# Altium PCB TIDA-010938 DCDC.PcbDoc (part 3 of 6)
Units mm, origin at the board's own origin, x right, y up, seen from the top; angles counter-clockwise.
Board outline 280 x 174.95 mm, 4 copper layers (Top Layer, Layer 1, Layer 2, Bottom Layer), stack 1.787 mm thick; 409 components, 218 nets, 1371 pads, 2268 vias.
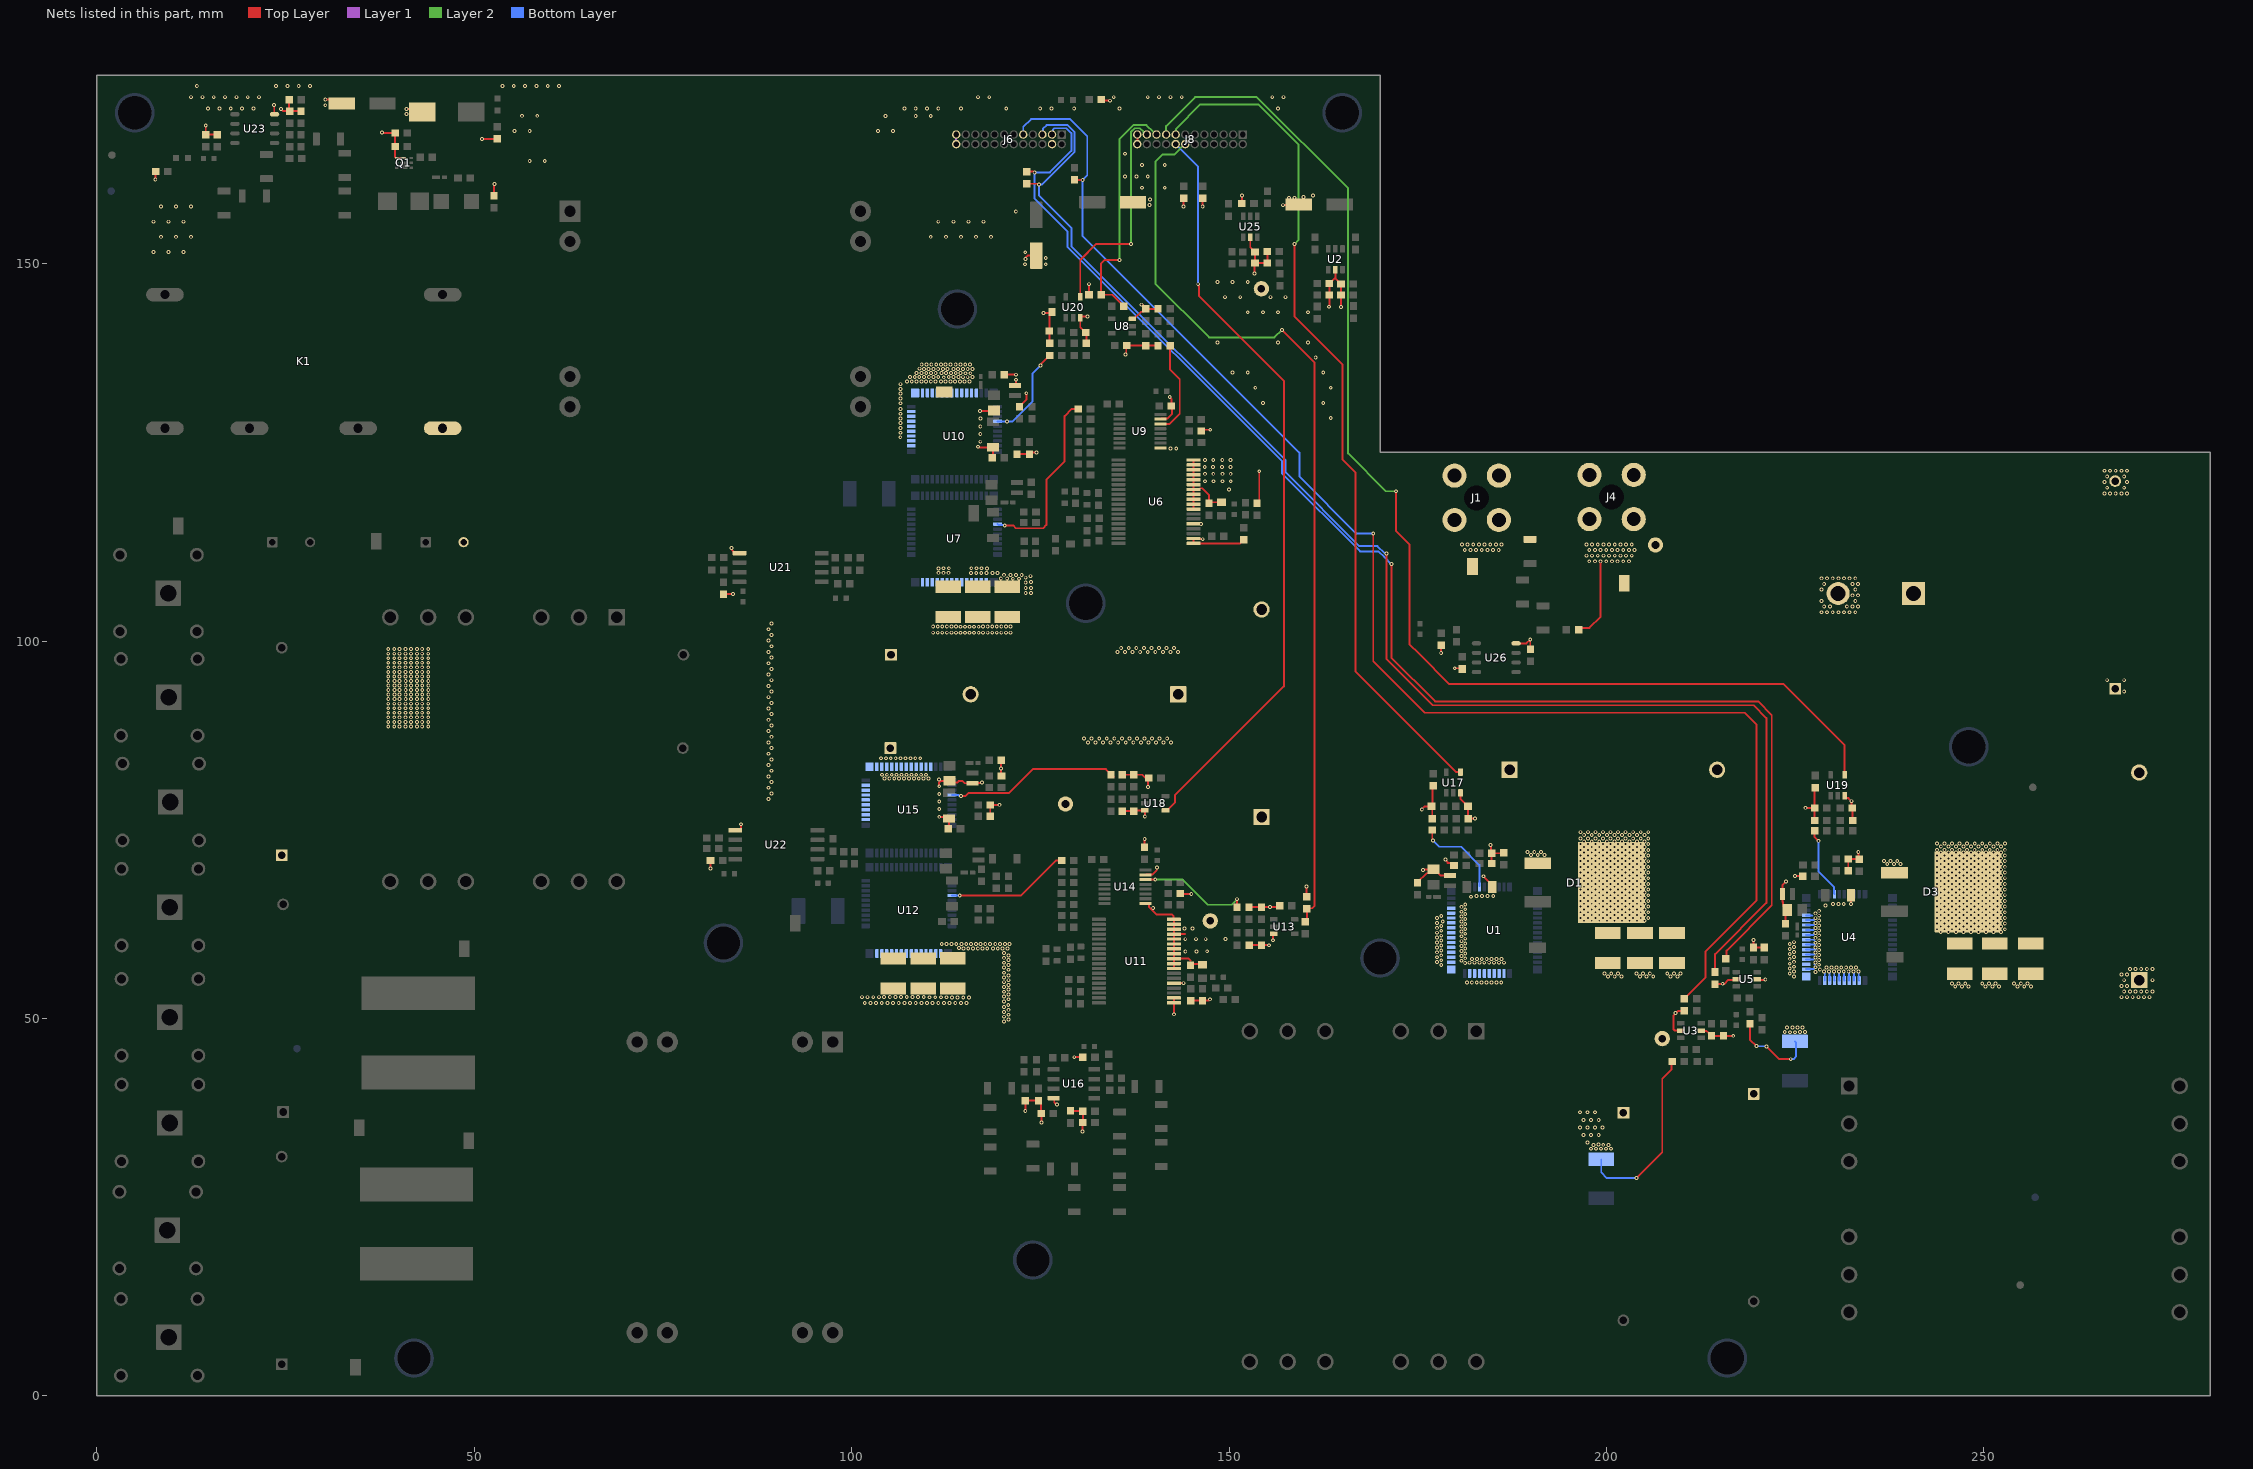
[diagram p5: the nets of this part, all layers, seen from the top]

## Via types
v1: diameter 0.508, hole 0.254, Top Layer to Bottom Layer, tented both sides, 1783 vias
v2: diameter 0.508, hole 0.254, Top Layer to Bottom Layer, 485 vias

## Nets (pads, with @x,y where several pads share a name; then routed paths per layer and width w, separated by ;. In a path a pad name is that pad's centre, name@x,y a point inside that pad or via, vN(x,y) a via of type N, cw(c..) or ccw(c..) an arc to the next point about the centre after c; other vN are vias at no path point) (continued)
CS_Boost1-: C19.1 J6.9 R146.2 | length 193.6
  Top Layer w0.254: C19.1@129.5,161.1 v1(130.6,161.1) ; v1(169.096,114.25) 169.096,97.304 175.9,90.5 218.3,90.5 219.9,88.9 219.9,65.659 213.1,58.859 213.1,55.425 210.3,52.625 R146.2@210.3,52.6
  Bottom Layer w0.254: J6.9@122.73,167.116 122.73,168.141 123.755,169.165 128.957,169.165 131.205,166.917 131.205,161.705 v1(130.6,161.1) 130.6,153.671 159.302,124.969 159.302,121.811 166.863,114.25 v1(169.096,114.25)
CS_Boost2+: C112.2 J6.3 R19.2 | length 186.7
  Top Layer w0.254: C112.2@123.184,162.2 124.077,162.2 124.174,162.103 v1(124.242,162.103) ; v1(171.5,110.207) 171.5,97.8 177.3,92 220.1,92 221.9,90.2 221.9,64.967 215.932,59 215.932,58.032 R19.2@215.8,57.9
  Bottom Layer w0.254: J6.3@126.54,167.116 126.675,167.251 126.675,167.804 126.823,167.953 128.455,167.953 129.1,167.308 129.1,164.936 126.267,162.103 v1(124.242,162.103) 124.242,158.625 128.585,154.283 128.585,152.276 156.995,123.865 156.995,122.259 167.37,111.884 169.795,111.884 170.592,111.087 170.62,111.087 v1(171.5,110.207)
CS_Boost2-: C112.1 J6.5 R72.2 | length 189.9
  Top Layer w0.254: C112.1@123.184,160.6 124.631,160.6 124.731,160.5 v1(124.8,160.5) ; v1(170.854,111.604) 170.854,97.646 177,91.5 219.5,91.5 221.2,89.8 221.2,65.323 214.4,58.523 R72.2@214.4,56.154
  Bottom Layer w0.254: J6.5@125.27,167.116 125.335,167.181 125.335,167.874 125.818,168.357 128.623,168.357 129.504,167.476 129.504,164.768 125.236,160.5 v1(124.8,160.5) 124.8,159.061 129.106,154.755 129.106,152.326 157.478,123.954 157.478,122.348 167.229,112.596 169.654,112.596 170.598,111.652 170.805,111.652 v1(170.854,111.604)
DC_Bus+: C3.1 C4.1 C10.1 C24.1 C100.1 C101.1 C106.1 C110.1 C111.1 C113.1 C114.2 C127.1 C130.1 C131.1 C135.1 C140.1 C141.1 C143.2 D1.1 D1.3 D3.1 D3.3 J1.1 R21.1 TP40.1 U7.2 U7.3 U7.4 U7.5 U7.6 U7.7 U7.8 U7.9 U7.10 U7.11 U7.12 U7.13 U7.14 U7.15 U12.2 U12.3 U12.4 U12.5 U12.6 U12.7 U12.8 U12.9 U12.10 U12.11 U12.12 U12.13 U12.14 U12.15
  other v1: 120.17,49.582 120.758,49.869 120.17,50.232 120.758,50.493 120.17,50.856 120.758,51.143 120.17,51.506 120.744,51.803 120.17,52.259 120.758,52.547 120.17,52.909 120.758,53.17 120.17,53.533 120.758,53.82 120.17,54.183 120.758,54.444 120.17,54.807 120.758,55.072 120.17,55.435 120.758,55.696 120.17,56.058 120.758,56.456 120.17,56.761 120.758,57.08 120.17,57.385 120.758,57.73 120.17,58.035 120.758,58.353 120.17,58.658 114.811,59.284 115.435,59.284 116.085,59.284 116.708,59.284 117.336,59.284 117.96,59.284 118.72,59.284 119.344,59.284 119.994,59.284 120.618,59.284 114.218,59.322 111.928,59.879 112.578,59.879 113.202,59.879 113.852,59.879 114.524,59.873 115.174,59.873 115.798,59.873 116.448,59.873 117.071,59.873 117.699,59.873 118.323,59.873 119.025,59.873 119.649,59.873 120.299,59.873 120.923,59.873 244.297,61.44 245.297,61.44 246.297,61.44 247.297,61.44 248.297,61.44 249.297,61.44 250.297,61.44 251.297,61.44 252.291,61.44 243.79,61.817 244.79,61.817 245.79,61.817 246.79,61.817 247.79,61.817 248.79,61.817 249.79,61.817 250.79,61.817 251.79,61.817 252.784,61.817 244.297,62.191 245.297,62.191 246.297,62.191 247.297,62.191 248.297,62.191 249.297,62.191 250.297,62.191 251.297,62.191 252.291,62.192 243.79,62.569 244.79,62.569 245.79,62.569 246.79,62.569 247.79,62.569 248.79,62.569 249.79,62.569 250.79,62.569 251.79,62.569 252.784,62.569 197.047,62.94 198.047,62.94 199.047,62.94 200.047,62.94 201.047,62.94 202.047,62.94 203.047,62.94 204.047,62.94 205.041,62.94 244.297,62.943 245.297,62.943 246.297,62.943 247.297,62.943 248.297,62.943 249.297,62.943 250.297,62.943 251.297,62.943 252.291,62.944 196.54,63.317 197.54,63.317 198.54,63.317 199.54,63.317 200.54,63.317 201.54,63.317 202.54,63.317 203.54,63.317 204.54,63.317 205.534,63.317 243.79,63.321 244.79,63.321 245.79,63.321 246.79,63.321 247.79,63.321 248.79,63.321 249.79,63.321 250.79,63.321 251.79,63.321 252.784,63.321 197.047,63.691 198.047,63.691 199.047,63.691 200.047,63.691 201.047,63.691 202.047,63.691 203.047,63.691 204.047,63.691 205.041,63.692 244.297,63.695 245.297,63.695 246.297,63.695 247.297,63.695 248.297,63.695 249.297,63.695 250.297,63.695 251.297,63.695 252.291,63.696 196.54,64.069 197.54,64.069 198.54,64.069 199.54,64.069 200.54,64.069 201.54,64.069 202.54,64.069 203.54,64.069 204.54,64.069 205.534,64.069 243.79,64.073 244.79,64.073 245.79,64.073 246.79,64.073 247.79,64.073 248.79,64.073 249.79,64.073 250.79,64.073 251.79,64.073 252.784,64.073 197.047,64.443 198.047,64.443 199.047,64.443 200.047,64.443 201.047,64.443 202.047,64.443 203.047,64.443 204.047,64.443 205.041,64.444 244.297,64.447 245.297,64.447 246.297,64.447 247.297,64.447 248.297,64.447 249.297,64.447 250.297,64.447 251.297,64.447 252.291,64.448 196.54,64.821 197.54,64.821 198.54,64.821 199.54,64.821 200.54,64.821 201.54,64.821 202.54,64.821 203.54,64.821 204.54,64.821 205.534,64.821 243.79,64.825 244.79,64.825 245.79,64.825 246.79,64.825 247.79,64.825 248.79,64.825 249.79,64.825 250.79,64.825 251.79,64.825 252.784,64.825 197.047,65.195 198.047,65.195 199.047,65.195 200.047,65.195 201.047,65.195 202.047,65.195 203.047,65.195 204.047,65.195 205.041,65.196 244.297,65.199 245.297,65.199 246.297,65.199 247.297,65.199 248.297,65.199 249.297,65.199 250.297,65.199 251.297,65.199 252.291,65.199 196.54,65.573 197.54,65.573 198.54,65.573 199.54,65.573 200.54,65.573 201.54,65.573 202.54,65.573 203.54,65.573 204.54,65.573 205.534,65.573 243.79,65.577 244.79,65.577 245.79,65.577 246.79,65.577 247.79,65.577 248.79,65.577 249.79,65.577 250.79,65.577 251.79,65.577 252.784,65.577 197.047,65.947 198.047,65.947 199.047,65.947 200.047,65.947 201.047,65.947 202.047,65.947 203.047,65.947 204.047,65.947 205.041,65.948 244.297,65.951 245.297,65.951 246.297,65.951 247.297,65.951 248.297,65.951 249.297,65.951 250.297,65.951 251.297,65.951 252.291,65.951 196.54,66.325 197.54,66.325 198.54,66.325 199.54,66.325 200.54,66.325 201.54,66.325 202.54,66.325 203.54,66.325 204.54,66.325 205.534,66.325 243.79,66.329 244.79,66.329 245.79,66.329 246.79,66.329 247.79,66.329 248.79,66.329 249.79,66.329 250.79,66.329 251.79,66.329 252.784,66.329 197.047,66.699 198.047,66.699 199.047,66.699 200.047,66.699 201.047,66.699 202.047,66.699 203.047,66.699 204.047,66.699 205.041,66.699 244.297,66.703 245.297,66.703 246.297,66.703 247.297,66.703 248.297,66.703 249.297,66.703 250.297,66.703 251.297,66.703 252.291,66.703 196.54,67.077 197.54,67.077 198.54,67.077 199.54,67.077 200.54,67.077 201.54,67.077 202.54,67.077 203.54,67.077 204.54,67.077 205.534,67.077 243.79,67.08 244.79,67.08 245.79,67.08 246.79,67.08 247.79,67.08 248.79,67.08 249.79,67.08 250.79,67.08 251.79,67.08 252.784,67.081 197.047,67.451 198.047,67.451 199.047,67.451 200.047,67.451 201.047,67.451 202.047,67.451 203.047,67.451 204.047,67.451 205.041,67.451 244.297,67.455 245.297,67.455 246.297,67.455 247.297,67.455 248.297,67.455 249.297,67.455 250.297,67.455 251.297,67.455 252.291,67.455 196.54,67.829 197.54,67.829 198.54,67.829 199.54,67.829 200.54,67.829 201.54,67.829 202.54,67.829 203.54,67.829 204.54,67.829 205.534,67.829 243.79,67.832 244.79,67.832 245.79,67.832 246.79,67.832 247.79,67.832 248.79,67.832 249.79,67.832 250.79,67.832 251.79,67.832 252.784,67.833 197.047,68.203 198.047,68.203 199.047,68.203 200.047,68.203 201.047,68.203 202.047,68.203 203.047,68.203 204.047,68.203 205.041,68.203 244.297,68.207 245.297,68.207 246.297,68.207 247.297,68.207 248.297,68.207 249.297,68.207 250.297,68.207 251.297,68.207 252.291,68.207 196.54,68.58 197.54,68.58 198.54,68.58 199.54,68.58 200.54,68.58 201.54,68.58 202.54,68.58 203.54,68.58 204.54,68.58 205.534,68.581 243.79,68.584 244.79,68.584 245.79,68.584 246.79,68.584 247.79,68.584 248.79,68.584 249.79,68.584 250.79,68.584 251.79,68.584 252.784,68.585 197.047,68.955 198.047,68.955 199.047,68.955 200.047,68.955 201.047,68.955 202.047,68.955 203.047,68.955 204.047,68.955 205.041,68.955 244.297,68.959 245.297,68.959 246.297,68.959 247.297,68.959 248.297,68.959 249.297,68.959 250.297,68.959 251.297,68.959 252.291,68.959 196.54,69.332 197.54,69.332 198.54,69.332 199.54,69.332 200.54,69.332 201.54,69.332 202.54,69.332 203.54,69.332 204.54,69.332 205.534,69.333 243.79,69.336 244.79,69.336 245.79,69.336 246.79,69.336 247.79,69.336 248.79,69.336 249.79,69.336 250.79,69.336 251.79,69.336 252.784,69.337 197.047,69.707 198.047,69.707 199.047,69.707 200.047,69.707 201.047,69.707 202.047,69.707 203.047,69.707 204.047,69.707 205.041,69.707 244.297,69.711 245.297,69.711 246.297,69.711 247.297,69.711 248.297,69.711 249.297,69.711 250.297,69.711 251.297,69.711 252.291,69.711 196.54,70.084 197.54,70.084 198.54,70.084 199.54,70.084 200.54,70.084 201.54,70.084 202.54,70.084 203.54,70.084 204.54,70.084 205.534,70.085 243.79,70.088 244.79,70.088 245.79,70.088 246.79,70.088 247.79,70.088 248.79,70.088 249.79,70.088 250.79,70.088 251.79,70.088 252.784,70.089 197.047,70.459 198.047,70.459 199.047,70.459 200.047,70.459 201.047,70.459 202.047,70.459 203.047,70.459 204.047,70.459 205.041,70.459 237.206,70.462 238.094,70.462 238.981,70.462 244.297,70.463 245.297,70.463 246.297,70.463 247.297,70.463 248.297,70.463 249.297,70.463 250.297,70.463 251.297,70.463 252.291,70.463 196.54,70.836 197.54,70.836 198.54,70.836 199.54,70.836 200.54,70.836 201.54,70.836 202.54,70.836 203.54,70.836 204.54,70.836 205.534,70.837 243.79,70.84 244.79,70.84 245.79,70.84 246.79,70.84 247.79,70.84 248.79,70.84 249.79,70.84 250.79,70.84 251.79,70.84 252.784,70.84 236.753,70.883 237.64,70.883 238.527,70.883 197.047,71.211 198.047,71.211 199.047,71.211 200.047,71.211 201.047,71.211 202.047,71.211 203.047,71.211 204.047,71.211 205.041,71.211 244.297,71.214 245.297,71.214 246.297,71.214 247.297,71.214 248.297,71.214 249.297,71.214 250.297,71.214 251.297,71.214 252.291,71.215 196.54,71.588 197.54,71.588 198.54,71.588 199.54,71.588 200.54,71.588 201.54,71.588 202.54,71.588 203.54,71.588 204.54,71.588 205.534,71.589 243.79,71.592 244.79,71.592 245.79,71.592 246.79,71.592 247.79,71.592 248.79,71.592 249.79,71.592 250.79,71.592 251.79,71.592 252.784,71.592 190.007,71.648 190.894,71.648 191.782,71.648 197.047,71.963 198.047,71.963 199.047,71.963 200.047,71.963 201.047,71.963 202.047,71.963 203.047,71.963 204.047,71.963 205.041,71.963 244.297,71.966 245.297,71.966 246.297,71.966 247.297,71.966 248.297,71.966 249.297,71.966 250.297,71.966 251.297,71.966 252.291,71.967 189.554,72.07 190.441,72.07 191.328,72.07 196.54,72.34 197.54,72.34 198.54,72.34 199.54,72.34 200.54,72.34 201.54,72.34 202.54,72.34 203.54,72.34 204.54,72.34 205.534,72.34 243.79,72.344 244.79,72.344 245.79,72.344 246.79,72.344 247.79,72.344 248.79,72.344 249.79,72.344 250.79,72.344 251.79,72.344 252.784,72.344 197.047,72.714 198.047,72.714 199.047,72.714 200.047,72.714 201.047,72.714 202.047,72.714 203.047,72.714 204.047,72.714 205.041,72.715 244.3,72.8 245.3,72.8 246.3,72.8 247.3,72.8 248.3,72.8 249.3,72.8 250.3,72.8 251.3,72.8 252.293,72.8 196.54,73.092 197.54,73.092 198.54,73.092 199.54,73.092 200.54,73.092 201.54,73.092 202.54,73.092 203.54,73.092 204.54,73.092 205.534,73.092 243.793,73.178 244.793,73.178 245.793,73.178 246.793,73.178 247.793,73.178 248.793,73.178 249.793,73.178 250.793,73.178 251.793,73.178 252.786,73.178 197.047,73.466 198.047,73.466 199.047,73.466 200.047,73.466 201.047,73.466 202.047,73.466 203.047,73.466 204.047,73.466 205.041,73.467 196.54,73.844 197.54,73.844 198.54,73.844 199.54,73.844 200.54,73.844 201.54,73.844 202.54,73.844 203.54,73.844 204.54,73.844 205.534,73.844 197.05,74.3 198.05,74.3 199.05,74.3 200.05,74.3 201.05,74.3 202.05,74.3 203.05,74.3 204.05,74.3 205.043,74.3 196.543,74.678 197.543,74.678 198.543,74.678 199.543,74.678 200.543,74.678 201.543,74.678 202.543,74.678 203.543,74.678 204.543,74.678 205.536,74.678 131.306,86.58 132.307,86.58 133.307,86.58 134.307,86.58 135.308,86.58 136.308,86.58 137.309,86.58 138.309,86.58 139.31,86.58 140.31,86.58 141.311,86.58 142.311,86.58 130.791,87.08 131.791,87.08 132.792,87.08 133.792,87.08 134.792,87.08 135.793,87.08 136.793,87.08 137.794,87.08 138.794,87.08 139.795,87.08 140.795,87.08 141.796,87.08 135.22,98.572 136.22,98.572 137.221,98.572 138.221,98.572 139.222,98.572 140.222,98.572 141.222,98.572 142.223,98.572 143.223,98.572 135.705,99.072 136.705,99.072 137.706,99.072 138.706,99.072 139.707,99.072 140.707,99.072 141.708,99.072 142.708,99.072 123.051,106.38 123.756,106.38 123.051,107.032 123.76,107.049 123.051,107.746 123.756,107.822 121.344,108.262 122.18,108.255 119.754,108.3 120.6,108.3 123.051,108.398 123.7,108.6 121.019,108.755 121.781,108.755 120.191,108.779 122.519,108.761 118.655,109.005 119.311,109.005 111.478,109.048 112.149,109.048 112.833,109.048 115.817,109.042 116.501,109.042 117.158,109.042 117.85,109.038 117.906,109.611 111.499,109.637 115.845,109.645 116.529,109.645 117.186,109.645 112.17,109.651 112.861,109.651
  other v2: 268.223,52.817 268.973,52.817 269.723,52.817 270.473,52.817 271.223,52.817 271.973,52.817 268.598,53.567 269.348,53.567 270.098,53.567 270.848,53.567 271.598,53.567 272.348,53.567 268.223,54.317 268.973,54.317 268.598,55.067 272.348,55.067 268.223,55.817 268.973,55.817 269.348,56.567 270.098,56.567 270.848,56.567 271.598,56.567 272.348,56.567 228.473,103.817 229.223,103.817 229.973,103.817 230.723,103.817 231.473,103.817 232.223,103.817 232.973,103.817 228.848,104.567 229.598,104.567 231.848,104.567 232.598,104.567 233.348,104.567 228.473,105.317 232.973,105.317 232.598,106.067 233.348,106.067 228.473,106.817 232.973,106.817 228.848,107.567 232.598,107.567 233.348,107.567 228.473,108.317 229.223,108.317 229.973,108.317 230.723,108.317 231.473,108.317 232.223,108.317 232.973,108.317 181.223,112.067 181.973,112.067 182.723,112.067 183.473,112.067 184.223,112.067 184.973,112.067 185.723,112.067 180.848,112.817 181.598,112.817 182.348,112.817 183.098,112.817 183.848,112.817 184.598,112.817 185.348,112.817 186.098,112.817 265.973,119.567 266.723,119.567 267.473,119.567 268.223,119.567 268.973,119.567 266.348,120.317 268.598,120.317 265.973,121.067 268.973,121.067 266.348,121.817 268.598,121.817 265.973,122.567 266.723,122.567 267.473,122.567 268.223,122.567 268.973,122.567
DC_Bus-: C1.1 C2.1 C3.2 C4.2 C5.2 C6.2 C7.1 C8.1 C9.1 C10.2 C11.1 C12.1 C13.2 C14.1 C15.1 C16.2 C17.2 C20.2 C21.1 C22.1 C23.1 C24.2 C25.1 C26.1 C27.2 C28.1 C29.1 C31.1 C32.2 C39.1 C43.1 C47.1 C49.2 C50.1 C52.2 C57.2 C58.1 C59.2 C60.1 C61.1 C62.1 C64.1 C65.2 C67.2 C73.1 C77.1 C78.2 C81.1 C82.2 C83.2 C84.1 C86.2 C87.2 C91.2 C92.1 C93.2 C94.1 C95.1 C96.1 C97.2 C98.1 C99.2 C100.2 C101.2 C102.1 C103.1 C104.1 C105.1 C106.2 C107.1 C108.1 C110.2 C111.2 C113.2 C114.1 C115.2 C116.1 C117.2 C118.1 C119.1 C120.1 C121.2 C122.1 C123.1 C124.2 C125.2 C127.2 C128.2 C129.2 C130.2 C131.2 C132.1 C135.2 C140.2 C141.2 C142.1 C143.1 C144.2 C146.2 C152.1 C155.1 J4.1 J6.23 J6.24 J8.23 J8.24 K1.2 L2.1 L5.1 L10.1 L14.1 Q1.4 Q1.7 R2.2 R6.1 R9.1 R12.2 R16.1 R17.2 R18.2 R20.1 R27.1 R39.1 R45.1 R52.1 R64.1 R70.1 R72.1 R79.1 R80.1 R81.1 R82.1 R90.1 R91.1 R92.1 R93.1 R99.1 R105.1 R106.2 R125.1 R127.1 R129.1 R131.1 R132.1 R135.1 R138.1 R139.2 R140.1 R145.2 R146.1 R147.1 R149.1 R150.1 R151.1 R153.1 R154.1 R156.1 R157.1 TP1.1 TP2.1 TP4.1 TP5.1 TP6.1 TP35.1 TP42.1 U1.18 U1.19 U1.20 U1.21 U1.22 U1.23 U1.24 U1.25 U1.27 U1.28 U1.29 U1.30 U1.31 U1.32 U1.33 U1.34 U1.35 U1.36 U1.37 U1.38 U1.39 U2.2 U3.2 U3.5 U4.18 U4.19 U4.20 U4.21 U4.22 U4.23 U4.24 U4.25 U4.27 U4.28 U4.29 U4.30 U4.31 U4.32 U4.33 U4.34 U4.35 U4.36 U4.37 U4.38 U4.39 U5.2 U5.5 U6.1 U6.2 U6.5 U6.8 U6.9 U6.10 U6.11 U6.12 U6.13 U6.14 U6.15 U6.16 U6.17 U6.18 U8.3 U9.9 U9.15 U10.18 U10.19 U10.20 U10.21 U10.22 U10.23 U10.24 U10.25 U10.27 U10.28 U10.29 U10.30 U10.31 U10.32 U10.33 U10.34 U10.35 U10.36 U10.37 U10.38 U10.39 U11.1 U11.2 U11.5 U11.8 U11.9 U11.10 U11.11 U11.12 U11.13 U11.14 U11.15 U11.16 U11.17 U11.18 U13.3 U14.9 U14.15 U15.18 U15.19 U15.20 U15.21 U15.22 U15.23 U15.24 U15.25 U15.27 U15.28 U15.29 U15.30 U15.31 U15.32 U15.33 U15.34 U15.35 U15.36 U15.37 U15.38 U15.39 U16.4 U17.3 U18.3 U19.3 U20.3 U21.5 U22.5 U23.4 U25.2 U26.4 | length 332.8
  Top Layer w0.254: v1(7.724,161.159) 7.724,162.175 R154.1@7.769,162.22 ; v1(14.411,168.299) C132.1@14.411,167.095 C155.1@15.933,167.095 ; v1(23.453,171.01) 23.489,170.974 23.489,169.841 U23.4@23.525,169.805 ; v1(24.4,170.5) 24.692,170.208 C104.1@25.533,170.208 ; R150.1@25.458,171.735 25.458,170.283 C104.1@25.533,170.208 ; R139.2@27.031,170.208 C104.1@25.533,170.208 ; v1(30.25,171.75) 31.923,171.75 C121.2@32.425,171.248 ; v1@37.848,167.315 R145.2@39.502,167.315 C16.2@39.502,165.52 39.502,164.132 39.619,164.016 Q1.4@39.694,164.016 Q1.7@40.574,164.016 ; v1(41,170.5) 42.7,170.5 C117.2@43.095,170.105 ; v1@51.028,166.531 R147.1@53.036,166.531 ; C1.1@52.616,159 v1@52.616,160.537 ; v1(81.278,69.861) 81.278,70.909 C57.2@81.289,70.92 ; C49.2@83,106.2 83.05,106.25 v1(84.25,106.25) ; v1(84.067,112.341) 84.116,112.292 84.116,112.076 84.528,111.664 U21.5@85.128,111.664 ; U22.5@84.564,74.93 85.136,74.93 85.309,75.103 85.309,75.707 v1(85.331,75.729) ; v1(111.599,76.719) 112.666,76.719 C93.2@112.887,76.497 112.887,75.198 C95.1@112.812,75.123 ; v1(111.599,80.763) 111.579,80.783 111.579,81.251 111.802,81.474 C99.2@112.946,81.474 113.169,81.251 113.979,81.251 114.172,81.445 114.714,81.445 114.991,81.168 116.02,81.168 L14.1@116.023,81.165 116.065,81.208 117.208,81.208 v1(117.25,81.25) ; v1(116.75,125.75) 116.819,125.75 116.902,125.667 C59.2@118.733,125.667 118.733,124.258 C61.1@118.708,124.233 ; v1(117,130.5) 118.78,130.5 C65.2@118.837,130.557 ; C98.1@118.355,76.799 R70.1@118.355,78.269 118.392,78.306 v1(119.585,78.306) ; C65.2@118.981,130.701 C65.2@119.337,131.057 ; v1@119.794,83.1 R138.1@119.794,84.205 ; v1(119.8,83.1) 119.8,82.157 C96.1@119.843,82.113 ; R135.1@120.235,135.296 v1(121.764,135.296) ; L10.1@121.651,133.874 121.764,133.987 v1(121.764,134.63) ; C64.1@121.904,124.776 R45.1@123.555,124.776 123.779,125 v1(124.5,125) ; C62.1@122.218,131.057 122.218,131.082 123.133,131.997 v1(123.133,132.834) ; v1(123,37.75) 123,39.105 R140.1@122.987,39.118 C105.1@124.745,39.118 124.745,39.093 125.104,38.734 R151.1@125.104,37.422 125.16,37.367 v1(125.16,36.201) ; v1(123.011,150.618) 123.059,150.667 123.059,150.843 123.291,151.074 C144.2@124.449,151.074 C144.2@124.47,151.053 ; v1(125.412,143.48) 126.427,143.48 C129.2@126.55,143.603 ; R91.1@126.225,139.236 R91.1@126.225,139.468 126.225,143.095 C129.2@126.55,143.42 ; U16.4@126.744,39.433 126.744,39.347 126.832,39.26 126.832,38.872 126.952,38.752 127.005,38.752 127.15,38.606 v1(127.219,38.606) ; R149.1@129.004,37.747 130.584,37.747 C103.1@130.634,37.697 R106.2@130.634,36.222 130.586,36.174 v1(130.586,35) ; v1(129.479,44.868) C102.1@130.634,44.868 ; U20.3@130.283,142.528 130.283,141.567 131.058,140.792 131.083,140.792 R93.1@131.083,139.47 R93.1@131.083,139.236 ; U20.3@130.283,142.845 130.446,143.008 v1(131.239,143.008) ; C14.1@131.436,145.886 v1(131.436,147.286) ; R153.1@133.07,171.775 133.245,171.6 v1(134.2,171.6) ; R82.1@135.833,77.469 137.333,77.469 137.427,77.563 U18.3@138.826,77.563 138.834,77.555 v1(138.834,76.741) ; R80.1@135.833,82.294 C78.2@137.378,82.294 138.5,82.294 C125.2@138.939,81.855 ; v1(136.283,137.964) 136.283,138.033 136.376,138.125 136.376,139.093 C52.2@136.431,139.148 C11.1@138.968,139.148 R39.1@140.566,139.148 ; U8.3@137.189,142.685 137.389,142.685 138.341,143.637 138.62,143.637 C15.1@138.968,143.985 ; C115.2@137.266,158.148 C115.2@138.168,158.148 ; J8.24@137.84,165.846 J8.23@137.84,167.116 ; v1(138.377,144.572) 138.426,144.523 138.588,144.523 138.618,144.493 138.618,144.358 C15.1@138.966,144.01 ; C84.1@138.8,72.668 138.8,73.749 v1@138.826,73.775 ; U14.9@138.941,65.223 139.293,65.223 139.361,65.155 139.361,64.803 140.405,63.759 142.449,63.759 142.631,63.577 142.631,63.175 U11.18@142.687,63.12 U11.17@142.687,62.47 U11.16@142.687,61.82 U11.15@142.687,61.17 ; U14.15@138.941,69.033 139,69.091 139.865,69.091 140.413,69.639 140.413,69.952 v1(140.451,69.991) ; C15.1@138.968,144.01 R64.1@140.564,144.01 ; C125.2@138.988,81.969 C125.2@139.015,81.941 ; C125.2@139.199,81.454 C125.2@139.199,81.87 ; v1(139.276,80.669) C125.2@139.276,81.956 ; U9.15@140.893,129.402 140.971,129.48 141.813,129.48 142.448,130.115 142.448,131.03 C50.1@142.316,131.162 142.343,131.188 142.343,132.086 142.142,132.286 v1(142.142,132.355) ; v1(142.687,50.55) U11.1@142.687,52.07 U11.2@142.687,52.72 ; U11.5@142.687,54.67 142.688,54.671 v1(143.962,54.672) v1(143.962,54.672) ; U11.8@142.687,56.62 U11.9@142.687,57.27 U11.10@142.687,57.92 ; C92.1@143.599,66.5 v1(144.993,66.5) ; v1(143.973,157.576) 143.973,158.662 C142.1@144,158.69 ; 144.16,61.153 144.152,61.162 142.695,61.162 U11.15@142.687,61.17 ; C77.1@144.887,57.06 145.064,57.237 C73.1@146.472,57.237 ; C81.1@144.912,52.357 147.289,52.357 147.463,52.532 v1(147.463,52.537) ; 144.912,57.642 144.635,57.92 U11.10@142.687,57.92 ; U6.5@145.299,115.54 145.319,115.52 146.284,115.52 v1(146.304,115.5) ; U6.8@145.299,117.49 U6.9@145.299,118.14 U6.10@145.299,118.79 U6.11@145.299,119.44 U6.12@145.299,120.09 ; U6.18@145.299,123.99 U6.17@145.299,123.34 U6.16@145.299,122.69 U6.15@145.299,122.04 U6.14@145.299,121.39 U6.13@145.299,120.74 U6.12@145.299,120.09 ; C58.1@146.329,128 v1(147.5,128) ; v1(146.5,157.596) C152.1@146.5,158.69 ; v1(146.508,113.5) 146.463,113.546 145.343,113.546 U6.2@145.299,113.59 U6.1@145.299,112.94 151.458,112.94 151.933,113.415 C47.1@151.933,113.44 ; C39.1@148.966,118.39 147.428,118.39 147.328,118.29 147.328,119.387 146.465,120.25 146.159,120.25 145.999,120.09 U6.12@145.299,120.09 ; C119.1@151.7,158 151.7,158.95 v1@151.75,159 ; R156.1@152.66,64.751 C25.1@154.276,64.751 156.519,64.751 156.803,65.036 C146.2@156.75,65.089 ; R157.1@152.661,59.728 C29.1@154.278,59.728 155.172,59.728 v1@155.2,59.7 ; U25.2@152.805,153.536 152.805,152.169 153.405,151.569 C120.1@153.43,151.569 R127.1@153.43,150.108 ; v1(153.363,148.704) 153.363,150.041 R127.1@153.43,150.108 ; R27.1@153.691,118.29 154,118.599 v1(154,122.5) ; C122.1@155.069,151.6 R125.1@155.069,150.108 R127.1@153.43,150.108 ; v1(155.8,60.361) 155.8,61.1 U13.3@155.925,61.225 ; v1(157.163,157.754) 159.172,157.754 C5.2@159.246,157.828 ; v1(160.269,67.5) 160.269,66.146 C28.1@160.3,66.115 ; v1@163.259,144.42 163.284,144.445 R131.1@163.284,145.864 C116.1@163.284,147.367 163.309,147.367 164,148.058 164.076,148.058 ; U2.2@164.076,149.208 164.076,148.058 ; v1@164.826,144.405 R129.1@164.826,145.869 C118.1@164.826,147.333 164.801,147.333 164.076,148.058 ; R105.1@174.956,68.031 176.168,69.242 176.554,69.242 C13.2@177.029,69.718 ; v1(175.534,77.669) 175.534,77.701 175.938,78.105 C67.2@176.819,78.105 ; v1(175.7,69.665) 175.769,69.665 175.821,69.718 C13.2@177.029,69.718 ; R79.1@176.915,76.459 C67.2@176.915,78.105 ; C67.2@176.966,78.156 C124.2@176.966,80.902 ; v1(178.1,98.431) 178.1,99.404 R99.1@178.116,99.42 ; v1(178.694,71.052) 178.694,70.983 178.92,70.757 178.92,70.647 178.957,70.61 179.453,70.61 C7.1@179.801,70.262 ; L2.1@179.25,68.934 178.043,68.934 177.227,69.75 C13.2@177.062,69.75 C13.2@177.029,69.718 ; v1(179.9,96.4) 180.8,96.4 C107.1@180.9,96.3 ; U17.3@180.669,79.869 U17.3@180.66,79.878 180.66,79.097 181.677,78.08 R81.1@181.677,76.459 ; R81.1@181.677,76.5 v1(182.6,76.5) ; v1(183.708,68.837) 184.886,67.659 C6.2@184.886,67.409 ; v1(184.651,73) 184.651,72.931 184.725,72.857 184.725,71.94 R6.1@184.776,71.89 ; C12.1@184.776,70.518 R6.1@184.776,71.89 ; C8.1@186.392,71.965 186.317,71.89 R6.1@184.776,71.89 ; U26.4@188.025,99.705 189.405,99.705 v1(189.9,100.2) 189.9,98.977 C123.1@189.823,98.9 ; R12.2@196.3,101.5 196.55,101.75 197.75,101.75 199.223,103.223 199.223,110.473 v2@199.25,110.5 ; v1(203.963,28.838) 207.396,32.271 207.396,41.996 208.6,43.2 208.6,44.2 R9.1@208.7,44.3 ; U3.2@209.825,48.4 209.049,48.4 208.9,48.549 208.9,50.4 209.475,50.975 R146.1@210.3,50.975 ; U3.5@212.575,48.4 212.663,48.312 213.288,48.312 213.527,48.073 213.552,48.073 213.9,47.725 C108.1@213.9,47.7 C17.2@215.3,47.7 ; R72.1@214.4,54.554 215.614,54.554 216.159,55.1 U5.2@217.225,55.1 ; C17.2@215.5,47.7 v1(216.8,47.7) ; R20.1@219,49.3 219,47.2 v1@219.9,46.3 ; v1(219.5,60.4) C32.2@219.5,59.4 C31.1@220.9,59.4 ; U5.5@219.975,55.1 220.948,55.1 v1@221,55.152 ; v1(221.2,46.3) 222.9,44.6 v1(224.416,44.6) ; R132.1@223.705,62.56 223.705,64.136 C27.2@223.895,64.326 ; v1(223.776,68.146) 223.776,68.116 223.348,67.688 223.348,66.537 L5.1@223.318,66.507 223.318,66.321 223.324,66.315 223.324,65.475 223.417,65.381 223.417,65.187 223.426,65.178 223.426,64.873 C27.2@223.934,64.365 ; v1(224.97,68.889) 225.977,68.889 C22.1@226.029,68.837 ; v1(226.354,77.907) 227.317,77.907 C86.2@227.585,78.174 ; R90.1@227.585,76.244 C86.2@227.585,77.863 C86.2@227.585,78.174 ; C128.2@227.66,80.588 227.585,80.513 C86.2@227.585,78.174 ; U19.3@231.59,79.513 231.59,79.36 231.763,79.187 232.064,79.187 v1@232.449,78.802 ; C26.1@232.032,69.563 R16.1@232.032,71.113 C21.1@233.369,71.113 ; C20.2@232.123,66.591 C20.2@232.394,66.321 232.383,66.31 v1(232.383,65.178) ; v1(232.463,78.788) 232.463,77.982 C91.2@232.582,77.863 ; R92.1@232.607,76.244 C91.2@232.607,77.863 ; v1(233.369,72.038) C21.1@233.369,71.113 ; C21.1@233.5,71.1 233.487,71.113 C21.1@233.369,71.113 ; U11.10@142.687,57.92 U11.11@142.687,58.57 U11.12@142.687,59.22 U11.13@142.687,59.87 U11.14@142.687,60.52 U11.15@142.687,61.17
  Layer 1 w0.254: J6.24@113.84,165.846 J6.23@113.84,167.116
  Bottom Layer w0.254: R17.2@199.305,31.341 199.305,29.598 200.065,28.838 v1(203.963,28.838) ; v1(219.894,46.342) 219.915,46.321 221.179,46.321 v1(221.2,46.3) ; v1(224.416,44.6) 224.429,44.614 224.792,44.614 225.1,44.922 225.1,46.84 R18.2@224.979,46.96 ; U4.28@226.459,56.525 227.478,56.525 ; U4.30@226.459,57.825 227.409,57.825 ; U4.31@226.459,58.475 227.542,58.475 ; U4.32@226.459,59.125 227.718,59.125 ; U4.33@226.459,59.775 227.563,59.775 227.625,59.713 ; U4.34@226.459,60.425 227.497,60.425 227.56,60.363 ; U4.35@226.459,61.075 227.41,61.075 227.667,61.332 v1(227.676,61.332) ; U4.36@226.459,61.725 227.392,61.725 227.409,61.742 ; U4.37@226.459,62.375 227.478,62.375 ; U4.38@226.459,63.025 227.516,63.025 227.535,63.006 ; U4.39@226.459,63.675 226.503,63.631 227.259,63.631 227.282,63.607 ; 227.564,57.175 227.625,57.114 ; U4.25@228.919,55.025 228.919,55.882 228.953,55.916 ; v1(229.495,56.239) 229.532,56.202 229.532,55.062 U4.24@229.569,55.025 ; v1(230.145,56.239) 230.182,56.202 230.182,55.062 U4.23@230.219,55.025 ; v1(230.795,56.239) 230.832,56.202 230.832,55.062 U4.22@230.869,55.025 ; v1(231.445,56.239) 231.482,56.202 231.482,55.062 U4.21@231.519,55.025 ; v1(232.095,56.239) 232.132,56.202 232.132,55.062 U4.20@232.169,55.025 ; v1(232.745,56.239) 232.782,56.202 232.782,55.062 U4.19@232.819,55.025 ; v1(233.395,56.239) 233.432,56.202 233.432,55.062 U4.18@233.469,55.025
  other v1: 197.964,32.737 198.632,32.737 199.282,32.737 199.932,32.737 200.582,32.737 198.302,33.245 199.58,33.255 200.252,33.245 198.93,33.281 224.329,48.174 224.992,48.174 223.627,48.188 225.629,48.188 226.3,48.2 223.938,48.821 224.659,48.821 225.333,48.821 225.959,48.821 209.146,50.713 246.217,54.217 247.104,54.217 247.991,54.217 250.244,54.217 251.131,54.217 252.018,54.217 254.465,54.217 255.353,54.217 256.24,54.217 215.4,54.6 245.763,54.638 246.65,54.638 247.537,54.638 249.79,54.638 250.677,54.638 251.564,54.638 254.012,54.638 254.899,54.638 255.786,54.638 181.511,54.746 182.161,54.746 182.811,54.746 183.461,54.746 184.111,54.746 184.761,54.746 185.411,54.746 186.061,54.746 221.046,55.165 200.201,55.554 201.088,55.554 201.975,55.554 204.423,55.554 205.31,55.554 206.197,55.554 208.505,55.554 209.392,55.554 224.833,55.554 224.286,55.95 199.747,55.975 200.634,55.975 201.521,55.975 203.969,55.975 204.856,55.975 205.743,55.975 208.051,55.975 208.938,55.975 209.825,55.975 227.676,56.132 224.833,56.204 228.827,56.239 228.269,56.489 224.286,56.6 229.165,56.747 229.815,56.747 230.465,56.747 231.115,56.747 231.765,56.747 232.415,56.747 233.065,56.747 227.676,56.782 224.833,56.854 178.108,57.064 228.184,57.113 224.286,57.25 181.281,57.363 181.861,57.387 182.511,57.387 183.161,57.387 183.811,57.387 184.461,57.387 185.111,57.387 185.761,57.387 186.411,57.387 227.676,57.432 177.561,57.46 224.833,57.504 180.788,57.639 178.108,57.714 228.184,57.763 182.181,57.895 182.831,57.895 183.481,57.895 184.131,57.895 184.781,57.895 185.431,57.895 186.081,57.895 224.286,57.9 181.296,57.97 227.676,58.082 177.561,58.11 224.833,58.154 180.788,58.289 178.108,58.364 228.184,58.413 224.286,58.55 181.296,58.62 227.676,58.732 177.561,58.76 224.833,58.804 144.2,58.871 145.7,58.871 147.1,58.9 180.788,58.939 178.108,59.014 228.184,59.063 224.286,59.2 181.296,59.27 227.676,59.382 177.561,59.41 224.833,59.454 180.788,59.589 178.108,59.664 155.3,59.703 228.184,59.713 224.286,59.85 181.296,59.92 227.676,60.032 177.561,60.06 224.833,60.104 180.788,60.239 178.108,60.314 228.184,60.363 144.2,60.5 145.6,60.5 146.9,60.5 149.529,60.506 181.296,60.57 227.676,60.682 177.561,60.71 180.788,60.889 178.108,60.964 228.184,61.013 181.296,61.22 177.561,61.36 180.788,61.539 178.108,61.614 228.184,61.663 181.296,61.87 144.071,61.917 145.171,61.917 227.676,61.982 177.561,62.01 180.788,62.189 178.108,62.264 228.184,62.313 181.296,62.52 227.676,62.632 177.561,62.66 178.314,62.839 180.788,62.839 228.184,62.963 181.296,63.17 227.676,63.282 177.561,63.31 180.788,63.489 178.108,63.564 228.184,63.613 181.296,63.82 227.676,63.932 180.788,64.139 228.184,64.263 181.296,64.47 139.942,64.639 155.4,64.774 180.788,64.789 229.003,64.948 181.296,65.12 230.022,65.178 230.742,65.178 231.445,65.178 182.037,66.12 182.777,66.232 183.518,66.232 184.258,66.232 184.999,66.232 138.815,73.781 111.599,77.73 111.599,78.741 111.599,79.752 111.579,81.669 104.331,81.78 104.981,81.78 105.631,81.78 106.281,81.78 106.931,81.78 107.581,81.78 108.231,81.78 108.881,81.78 109.531,81.78 110.181,81.78 104.001,82.288 104.651,82.288 105.301,82.288 105.951,82.288 106.601,82.288 107.251,82.288 107.901,82.288 108.551,82.288 109.201,82.288 109.851,82.288 103.876,84.476 104.526,84.476 105.176,84.476 105.826,84.476 106.476,84.476 107.126,84.476 107.776,84.476 108.426,84.476 109.076,84.476 38.587,88.698 39.387,88.698 40.087,88.698 40.887,88.698 41.587,88.698 42.387,88.698 43.087,88.698 43.887,88.698 38.587,89.3 39.387,89.3 40.087,89.3 40.887,89.3 41.587,89.3 42.387,89.3 43.087,89.3 43.887,89.3 38.587,89.902 39.387,89.902 40.087,89.902 40.887,89.902 41.587,89.902 42.387,89.902 43.087,89.902 43.887,89.902 38.587,90.504 39.387,90.504 40.087,90.504 40.887,90.504 41.587,90.504 42.387,90.504 43.087,90.504 43.887,90.504 38.587,91.105 39.387,91.105 40.087,91.105 40.887,91.105 41.587,91.105 42.387,91.105 43.087,91.105 43.887,91.105 38.587,91.707 39.387,91.707 40.087,91.707 40.887,91.707 41.587,91.707 42.387,91.707 43.087,91.707 43.887,91.707 38.599,92.322 39.399,92.322 40.099,92.322 40.899,92.322 41.599,92.322 42.399,92.322 43.099,92.322 43.899,92.322 38.599,92.924 39.399,92.924 40.099,92.924 40.899,92.924 41.599,92.924 42.399,92.924 43.099,92.924 43.899,92.924 268.598,93.317 38.599,93.526 39.399,93.526 40.099,93.526 40.899,93.526 41.599,93.526 42.399,93.526 43.099,93.526 43.899,93.526 38.599,94.127 39.399,94.127 40.099,94.127 40.899,94.127 41.599,94.127 42.399,94.127 43.099,94.127 43.899,94.127 38.599,94.729 39.399,94.729 40.099,94.729 40.899,94.729 41.599,94.729 42.399,94.729 43.099,94.729 43.899,94.729 266.348,94.817 268.598,94.817 38.587,95.318 39.387,95.318 40.087,95.318 40.887,95.318 41.587,95.318 42.387,95.318 43.087,95.318 43.887,95.318 38.587,95.92 39.387,95.92 40.087,95.92 40.887,95.92 41.587,95.92 42.387,95.92 43.087,95.92 43.887,95.92 38.587,96.522 39.387,96.522 40.087,96.522 40.887,96.522 41.587,96.522 42.387,96.522 43.087,96.522 43.887,96.522 38.587,97.124 39.387,97.124 40.087,97.124 40.887,97.124 41.587,97.124 42.387,97.124 43.087,97.124 43.887,97.124 38.587,97.726 39.387,97.726 40.087,97.726 40.887,97.726 41.587,97.726 42.387,97.726 43.087,97.726 43.887,97.726 38.587,98.328 39.387,98.328 40.087,98.328 40.887,98.328 41.587,98.328 42.387,98.328 43.087,98.328 43.887,98.328 38.587,98.93 39.387,98.93 40.087,98.93 40.887,98.93 41.587,98.93 42.387,98.93 43.087,98.93 43.887,98.93 114.415,101.101 115.017,101.101 115.619,101.101 116.22,101.101 116.822,101.101 110.791,101.113 111.393,101.113 111.995,101.113 112.597,101.113 113.198,101.113 113.8,101.113 117.411,101.113 118.013,101.113 118.615,101.113 119.217,101.113 119.819,101.113 120.421,101.113 121.022,101.113 110.791,101.913 111.393,101.913 111.995,101.913 112.597,101.913 113.198,101.913 113.8,101.913 114.415,101.901 115.017,101.901 115.619,101.901 116.22,101.901 116.822,101.901 117.411,101.913 118.013,101.913 118.615,101.913 119.217,101.913 119.819,101.913 120.421,101.913 121.022,101.913 149.984,120.082 146.823,121.176 147.923,121.176 149.123,121.176 150.223,121.176 146.81,122.161 147.91,122.161 149.11,122.161 150.21,122.161 146.771,123.067 147.871,123.067 149.071,123.067 150.171,123.067 146.8,124 147.9,124 149.1,124 150.2,124 142.25,125.5 143,125.5 117.039,126.418 106.439,127.009 117.039,127.429 106.476,127.601 106.476,128.225 117.039,128.44 106.476,128.875 106.476,129.499 117.082,129.508 106.476,130.127 106.476,130.75 106.476,131.511 106.476,132.134 106.476,132.784 106.476,133.408 106.476,134.036 114.332,134.379 114.955,134.379 115.605,134.379 107.305,134.409 107.955,134.409 108.579,134.409 109.229,134.409 109.852,134.409 110.48,134.409 111.104,134.409 111.806,134.409 112.43,134.409 113.08,134.409 113.704,134.409 112.194,134.949 114.739,134.968 115.367,134.968 108.352,134.986 108.942,134.972 109.592,134.972 110.216,134.972 110.844,134.972 111.467,134.972 112.851,134.972 113.501,134.972 114.125,134.972 116.002,134.986 107.726,135.01 115.083,135.492 115.711,135.492 108.601,135.538 109.25,135.538 109.874,135.538 110.502,135.538 111.126,135.538 111.886,135.538 112.51,135.538 113.16,135.538 113.783,135.538 114.411,135.538 109.558,136.056 110.181,136.056 110.831,136.056 111.455,136.056 112.083,136.056 112.707,136.056 113.467,136.056 114.091,136.056 114.741,136.056 115.364,136.056 115.992,136.056 108.965,136.093 109.271,136.644 109.921,136.644 110.544,136.644 111.194,136.644 111.818,136.644 112.446,136.644 113.069,136.644 113.772,136.644 114.396,136.644 115.046,136.644 115.669,136.644 164.813,144.278 163.247,144.293 122.97,149.932 125.702,149.932 125.702,150.768 122.991,151.515 121.742,156.94 139.441,157.784 139.5,158.5 157.926,158.742 158.646,158.742 159.842,158.819 151.719,159.026 161.124,159.039 52.646,160.542 51.026,166.532 37.74,167.401 40.994,169.816 30.25,171
  other v2: 197.473,33.566 196.973,34.566 197.973,34.566 198.973,34.566 196.473,35.566 197.473,35.566 198.473,35.566 199.473,35.566 196.973,36.566 197.973,36.566 198.973,36.566 196.473,37.566 197.473,37.566 198.473,37.566 101.723,52.067 102.473,52.067 103.223,52.067 103.973,52.067 104.723,52.067 105.473,52.067 106.223,52.067 106.973,52.067 107.723,52.067 108.473,52.067 109.223,52.067 109.973,52.067 110.723,52.067 111.473,52.067 112.223,52.067 112.973,52.067 113.723,52.067 114.473,52.067 115.223,52.067 113.278,52.761 114.028,52.761 114.778,52.761 115.528,52.761 101.348,52.817 102.098,52.817 102.848,52.817 103.598,52.817 110.32,52.806 111.07,52.806 111.82,52.806 112.57,52.806 104.298,52.828 105.048,52.828 105.798,52.828 106.548,52.828 107.291,52.832 108.041,52.832 108.791,52.832 109.541,52.832 88.973,79.067 89.348,79.817 88.973,80.567 89.348,81.317 88.973,82.067 89.348,82.817 88.973,83.567 89.348,84.317 88.973,85.067 89.348,85.817 88.973,86.567 89.348,87.317 88.973,88.067 89.348,88.817 88.973,89.567 89.348,90.317 88.973,91.067 89.348,91.817 88.973,92.567 89.348,93.317 88.973,94.067 89.348,94.817 88.973,95.567 89.348,96.317 88.973,97.067 89.348,97.817 88.973,98.567 89.348,99.317 88.973,100.067 89.348,100.817 88.973,101.567 89.348,102.317 197.723,110.567 198.473,110.567 199.223,110.567 199.973,110.567 200.723,110.567 201.473,110.567 202.223,110.567 202.973,110.567 197.348,111.317 198.098,111.317 198.848,111.317 199.598,111.317 200.348,111.317 201.098,111.317 201.848,111.317 202.598,111.317 203.348,111.317 197.723,112.067 198.473,112.067 199.223,112.067 199.973,112.067 200.723,112.067 201.473,112.067 202.223,112.067 202.973,112.067 203.723,112.067 197.348,112.817 198.098,112.817 198.848,112.817 199.598,112.817 200.348,112.817 201.098,112.817 201.848,112.817 202.598,112.817 203.348,112.817 163.473,129.566 154.473,131.566 162.473,131.566 153.473,133.566 163.473,133.566 150.473,135.566 152.473,135.566 162.473,135.566 161.473,137.566 148.473,139.566 156.473,139.566 160.473,139.566 152.473,143.566 154.473,143.566 156.473,143.566 160.473,143.566 149.473,145.566 151.473,145.566 155.473,145.566 157.473,145.566 148.473,147.566 150.473,147.566 152.473,147.566 7.473,151.566 9.473,151.566 11.473,151.566 8.473,153.566 10.473,153.566 12.473,153.566 110.473,153.566 112.473,153.566 114.473,153.566 116.473,153.566 118.473,153.566 7.473,155.566 9.473,155.566 11.473,155.566 111.473,155.566 113.473,155.566 115.473,155.566 117.473,155.566 8.473,157.566 10.473,157.566 12.473,157.566 138.473,160.066 141.473,160.066 136.223,161.566 137.723,161.566 139.223,161.566 138.473,163.066 141.473,163.066 57.328,163.6 59.328,163.6 136.223,164.566 103.473,167.567 105.473,167.567 55.328,167.6 57.328,167.6 104.473,169.567 108.473,169.567 110.473,169.567 56.328,169.6 58.328,169.6 14.723,170.566 16.223,170.566 17.723,170.566 19.223,170.566 20.723,170.566 106.973,170.566 108.473,170.566 109.973,170.566 111.473,170.566 114.473,170.566 120.473,170.566 124.973,170.566 126.473,170.566 129.473,170.566 135.473,170.566 156.473,170.566 12.473,172.066 13.973,172.066 15.473,172.066 16.973,172.066 18.473,172.066 19.973,172.066 21.473,172.066 116.723,172.066 118.223,172.066 134.723,172.066 139.223,172.066 140.723,172.066 142.223,172.066 143.723,172.066 155.723,172.066 157.223,172.066 13.223,173.566 23.723,173.566 25.223,173.566 26.723,173.566 28.223,173.566 53.723,173.566 55.223,173.566 56.723,173.566 58.223,173.566 59.723,173.566 61.223,173.566
Enable_Buffer_DCDC: J6.4
F\A\U\L\T\__Bat_H1_Buff: R3.1 U9.14 | length 12.7
  Top Layer w0.254: U9.14@140.893,128.767 142.137,128.767 143.465,130.095 143.465,134.714 142.197,135.982 R3.1@142.197,139.148
F\A\U\L\T\_Bat_H1_init: R34.2 U7.46 | length 24.5
  Top Layer w0.254: v1(120.272,115.33) 121.383,115.33 121.764,114.95 125.35,114.95 125.796,115.396 125.796,121.389 128.216,123.809 128.216,129.801 129.178,130.763 R34.2@130.039,130.763
  Bottom Layer w0.254: U7.46@119.333,115.494 119.431,115.396 120.138,115.396 120.204,115.33 v1(120.272,115.33)
F\A\U\L\T\_Bat_H2_Buff: R13.1 U14.14 | length 14.9
  Top Layer w0.254: U14.14@138.941,68.398 138.953,68.409 140.201,68.409 v1(140.212,68.421) ; R13.1@151.043,64.751 151.05,64.758 v1(151.05,65.8)
  Layer 2 w0.254: v1(140.212,68.421) 140.201,68.409 143.834,68.409 147.175,65.069 150.369,65.069 v1@151.042,65.742
F\A\U\L\T\_Bat_H2_init: R59.2 U12.46 | length 16.4
  Top Layer w0.254: v1(114.307,66.289) 122.427,66.289 127.072,70.934 127.799,70.934 R59.2@127.804,70.94
  Bottom Layer w0.254: U12.46@113.287,66.289 v1(114.307,66.289)
F\A\U\L\T\_Bat_L1_init: R84.1 U10.46 | length 12.8
  Top Layer w0.254: v1(125,136.5) 125.049,136.549 125.049,136.686 126,137.637 R84.1@126,138
  Bottom Layer w0.254: U10.46@119.317,129.115 120.563,129.115 v1(120.569,129.109) 121.314,129.109 123.942,131.737 123.942,135.442 v1(125,136.5)
F\A\U\L\T\_Bat_L2_init: R76.1 U15.46 | length 23.4
  Top Layer w0.254: v1(114.463,79.472) 114.481,79.49 115.097,79.49 115.459,79.852 120.451,79.852 120.485,79.886 120.87,79.886 124.011,83.027 133.675,83.027 R76.1@134.692,82.01
  Bottom Layer w0.254: U15.46@113.287,79.606 114.126,79.606 114.211,79.521 114.415,79.521 v1(114.463,79.472)
F\A\U\L\T\_Boost1_init: R75.1 U1.46 | length 11.7
  Top Layer w0.254: R75.1@176.915,74.959 176.915,73.75 177.031,73.634 v1(177.031,73.565)
  Bottom Layer w0.254: v1(177.031,73.565) 177.846,72.75 180.75,72.75 183.176,70.324 183.176,69.85 183.187,69.839 183.187,69.399 183.176,69.388 U1.46@183.176,67.517
F\A\U\L\T\_Boost2_init: R83.1 U4.46 | length 9.7
  Top Layer w0.254: R83.1@227.585,75.112 227.585,74.03 v1(228.076,73.538)
  Bottom Layer w0.254: v1(228.076,73.538) 228.076,69.492 230.138,67.431 230.138,66.556 U4.46@230.219,66.475
F\A\U\L\T\_O\C\_Batt_H1_Buff: C14.2 J8.19 R4.2 | length 32.8
  Top Layer w0.254: v1(135.5,150.5) 133.5,150.5 133.036,150.036 C14.2@133.036,145.886 134.491,145.886 136.011,144.367 R4.2@136.036,144.367
  Layer 2 w0.254: v1(135.5,150.5) 135.5,166.531 137.326,168.357 139.053,168.357 139.947,167.463 139.947,167.116 J8.19@140.38,167.116
F\A\U\L\T\_O\C\_Batt_H2_Buff: C28.2 J8.14 R14.2 | length 122.3
  Top Layer w0.254: v1(157.017,141.234) 157.017,141.197 161.3,136.913 161.3,64.899 161.007,64.606 160.391,64.606 C28.2@160.3,64.515 160.3,63 R14.2@160.1,62.8
  Layer 2 w0.254: J8.14@144.123,165.866 142.709,164.451 141.149,164.451 140.226,163.529 140.226,147.352 147.349,140.229 156.012,140.229 v1(157.017,141.234)
F\A\U\L\T\_O\C\_Batt_L1_Buff: J8.21 U20.4 | length 30.1
  Top Layer w0.254: U20.4@130.283,145.656 130.283,150.493 132.409,152.619 v1(137.003,152.619)
  Layer 2 w0.254: v1(137.003,152.619) 137.003,167.463 137.493,167.953 138.187,167.953 138.677,167.463 138.677,167.116 J8.21@139.11,167.116
F\A\U\L\T\_O\C\_Batt_L2_Buff: J8.16 U18.4 | length 100.8
  Top Layer w0.254: U18.4@141.576,77.563 141.776,77.563 142.808,78.594 142.808,79.548 157.25,93.99 157.25,134.486 146,145.736 146,147.013 145.955,147.058 145.955,147.238 v1(145.906,147.286)
  Bottom Layer w0.254: J8.16@142.92,165.846 145.892,162.874 145.892,147.301 v1(145.906,147.286)
F\A\U\L\T\_O\C\_Boost1_Buff: J8.15 U17.4 | length 113.4
  Top Layer w0.254: v1(158.668,152.611) 158.668,142.989 165.03,136.627 165.03,124.053 166.75,122.333 166.75,95.95 180.072,82.628 U17.4@180.66,82.628
  Layer 2 w0.254: J8.15@142.92,167.116 142.972,167.168 142.972,167.887 146.188,171.103 153.889,171.103 159.177,165.815 159.177,153.12 v1(158.668,152.611)
F\A\U\L\T\_O\C\_Boost2_Buff: J8.17 U19.4 | length 163.3
  Top Layer w0.254: v1(172.1,119.85) 172.129,119.821 172.129,114.571 173.9,112.8 173.9,99.6 175.2,98.3 179.2,94.3 223.485,94.3 231.563,86.223 U19.4@231.563,82.436
  Layer 2 w0.254: J8.17@141.65,167.116 141.65,168.22 145.493,172.063 153.669,172.063 165.759,159.972 165.759,124.868 170.777,119.85 v1(172.1,119.85)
